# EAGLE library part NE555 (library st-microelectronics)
General purpose bipolar Timer
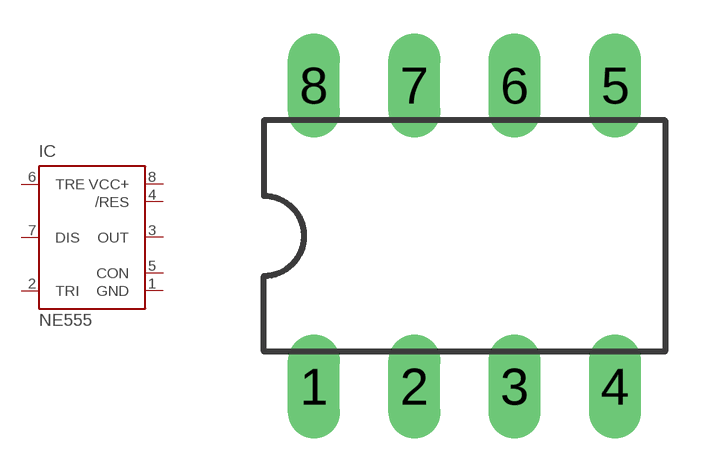
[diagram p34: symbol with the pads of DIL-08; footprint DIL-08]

Designator prefix IC

## NE555 (MF: Arrow Electronics; MPN: NE555N; OC_FARNELL: 1467742; OC_NEWARK: 89K1486)  [DIL-08]
1  GND  pwr
2  TRI  in
3  OUT  out
4  /RES  in
5  CON  in
6  TRE  in
7  DIS  in
8  VCC+  pwr

## Footprint DIL-08 (pad centres in mm)
Dual In Line Package
drill 0.813 long: 1 -3.81,-3.81; 2 -1.27,-3.81; 3 1.27,-3.81; 4 3.81,-3.81; 5 3.81,3.81; 6 1.27,3.81; 7 -1.27,3.81; 8 -3.81,3.81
